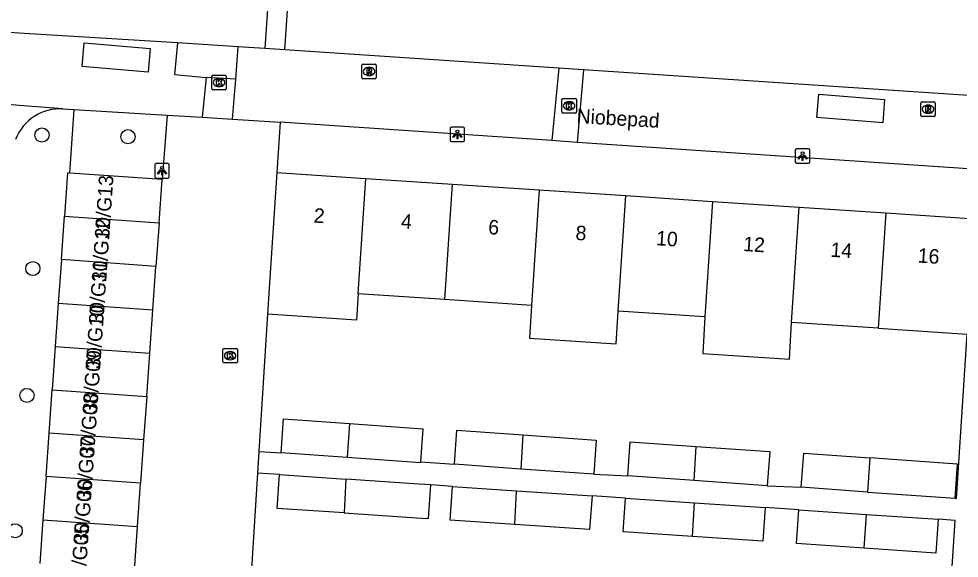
# Model space of a CAD drawing. Extents: x 161848 to 162726, y 385382 to 386521.
# Drawn here: x 162036.5 to 162101.4, y 385774.8 to 385812.1 of the extents above; entities that cross this region are included whole.
import ezdxf

# ---------------------------------------------------------------- set-up
doc = ezdxf.new("R2010")
doc.units = 0
for name, color, linetype in [('IMGEO_Boom', 7, 'Continuous'), ('IMGEO_Kolk', 7, 'Continuous'), ('IMGEO_Lichtpunt', 7, 'Continuous'), ('IMGEO_Muur', 7, 'Continuous'), ('IMGEO_Openbare_ruimte_label', 7, 'Continuous'), ('IMGEO_Pand', 7, 'Continuous'), ('IMGEO_Pand_nummerreeks', 7, 'Continuous'), ('IMGEO_Parkeervlak_open', 7, 'Continuous'), ('IMGEO_Rijbaan_lokaal_open', 7, 'Continuous'), ('IMGEO_Rioolput', 7, 'Continuous'), ('IMGEO_Voetpad_open', 7, 'Continuous'), ('IMGEO_Woonerf_open', 7, 'Continuous')]:
    doc.layers.add(name, color=color, linetype=linetype)

msp = doc.modelspace()

# ---------------------------------------------------------------- linework, layer by layer
at = {"layer": 'IMGEO_Boom'}
for centre in [(162038.108, 385804.041), (162044.038, 385803.929), (162037.475, 385794.824), (162037.071, 385786.061), (162036.258, 385776.72)]:
    msp.add_circle(centre, 0.489, dxfattribs=at)
at = {"layer": 'IMGEO_Kolk'}
for p, q in [((162049.821, 385807.242), (162049.821, 385808.094)), ((162049.896, 385808.168), (162050.748, 385808.168)), ((162050.309, 385807.948), (162050.334, 385807.948)), ((162050.822, 385808.094), (162050.822, 385807.242)), ((162050.332, 385807.388), (162050.307, 385807.388)), ((162050.748, 385807.168), (162049.896, 385807.168)), ((162073.969, 385805.636), (162073.969, 385806.488)), ((162074.044, 385806.562), (162074.896, 385806.562)), ((162074.457, 385806.342), (162074.482, 385806.342)), ((162074.97, 385806.488), (162074.97, 385805.636)), ((162074.896, 385805.562), (162074.044, 385805.562)), ((162074.48, 385805.782), (162074.455, 385805.782)), ((162050.589, 385788.38), (162050.589, 385789.232)), ((162050.664, 385789.306), (162051.516, 385789.306)), ((162051.59, 385789.232), (162051.59, 385788.38)), ((162051.1, 385788.526), (162051.075, 385788.526)), ((162051.077, 385789.086), (162051.102, 385789.086)), ((162051.516, 385788.306), (162050.664, 385788.306))]:
    msp.add_line(p, q, dxfattribs=at)
for points in [[(162049.821, 385807.242), (162049.821, 385808.094)], [(162049.896, 385808.168), (162050.748, 385808.168)], [(162050.822, 385808.094), (162050.822, 385807.242)], [(162050.142, 385807.868), (162050.265, 385807.868), (162050.265, 385807.717), (162050.395, 385807.868), (162050.559, 385807.868), (162050.413, 385807.717), (162050.566, 385807.468), (162050.414, 385807.468), (162050.329, 385807.632), (162050.265, 385807.565), (162050.265, 385807.468), (162050.142, 385807.468), (162050.142, 385807.868)], [(162050.748, 385807.168), (162049.896, 385807.168)], [(162073.969, 385805.636), (162073.969, 385806.488)], [(162074.044, 385806.562), (162074.896, 385806.562)], [(162074.29, 385806.262), (162074.413, 385806.262), (162074.413, 385806.111), (162074.543, 385806.262), (162074.707, 385806.262), (162074.561, 385806.111), (162074.714, 385805.862), (162074.562, 385805.862), (162074.477, 385806.026), (162074.413, 385805.959), (162074.413, 385805.862), (162074.29, 385805.862), (162074.29, 385806.262)], [(162074.97, 385806.488), (162074.97, 385805.636)], [(162074.896, 385805.562), (162074.044, 385805.562)], [(162050.589, 385788.38), (162050.589, 385789.232)], [(162050.664, 385789.306), (162051.516, 385789.306)], [(162051.59, 385789.232), (162051.59, 385788.38)], [(162050.91, 385789.006), (162051.033, 385789.006), (162051.033, 385788.855), (162051.163, 385789.006), (162051.327, 385789.006), (162051.181, 385788.855), (162051.334, 385788.606), (162051.182, 385788.606), (162051.097, 385788.77), (162051.033, 385788.703), (162051.033, 385788.606), (162050.91, 385788.606), (162050.91, 385789.006)], [(162051.516, 385788.306), (162050.664, 385788.306)]]:
    msp.add_lwpolyline(points, dxfattribs=at)
for centre, start, end in [((162049.898, 385808.092), 91.55205, 178.44795), ((162049.898, 385808.092), 91.55205, 178.44795), ((162050.746, 385808.092), 1.55205, 88.44795), ((162050.746, 385808.092), 1.55205, 88.44795), ((162049.898, 385807.244), 181.55205, 268.44795), ((162049.898, 385807.244), 181.55205, 268.44795), ((162050.746, 385807.244), 271.55205, 358.44795), ((162050.746, 385807.244), 271.55205, 358.44795), ((162074.046, 385806.486), 91.55205, 178.44795), ((162074.046, 385806.486), 91.55205, 178.44795), ((162074.894, 385806.486), 1.55205, 88.44795), ((162074.894, 385806.486), 1.55205, 88.44795), ((162074.046, 385805.638), 181.55205, 268.44795), ((162074.046, 385805.638), 181.55205, 268.44795), ((162074.894, 385805.638), 271.55205, 358.44795), ((162074.894, 385805.638), 271.55205, 358.44795), ((162050.666, 385789.23), 91.55205, 178.44795), ((162050.666, 385789.23), 91.55205, 178.44795), ((162051.514, 385789.23), 1.55205, 88.44795), ((162051.514, 385789.23), 1.55205, 88.44795), ((162050.666, 385788.382), 181.55205, 268.44795), ((162050.666, 385788.382), 181.55205, 268.44795), ((162051.514, 385788.382), 271.55205, 358.44795), ((162051.514, 385788.382), 271.55205, 358.44795)]:
    msp.add_arc(centre, 0.0765, start, end, dxfattribs=at)
for centre, major_axis, ratio, start_param, end_param in [((162050.308, 385807.668), (-0.387, 0.002), 0.722429, 4.712389, 7.853982), ((162050.333, 385807.668), (-0.39, 0.002), 0.717154, 1.570796, 4.712389), ((162074.456, 385806.062), (-0.387, 0.002), 0.722429, 4.712389, 7.853982), ((162074.481, 385806.062), (-0.39, 0.002), 0.717154, 1.570796, 4.712389), ((162051.076, 385788.806), (-0.387, 0.002), 0.722429, 4.712389, 7.853982), ((162051.101, 385788.806), (-0.39, 0.002), 0.717154, 1.570796, 4.712389)]:
    msp.add_ellipse(centre, major_axis=major_axis, ratio=ratio, start_param=start_param, end_param=end_param, dxfattribs=at)
at = {"layer": 'IMGEO_Lichtpunt'}
for p, q in [((162066.266, 385804.49), (162066.266, 385803.683)), ((162066.266, 385804.49), (162066.266, 385803.683)), ((162067.168, 385804.585), (162066.36, 385804.585)), ((162067.168, 385804.585), (162066.36, 385804.585)), ((162067.262, 385803.683), (162067.262, 385804.49)), ((162067.262, 385803.683), (162067.262, 385804.49)), ((162066.36, 385803.589), (162067.168, 385803.589)), ((162066.36, 385803.589), (162067.168, 385803.589)), ((162090.073, 385802.993), (162090.073, 385802.186)), ((162090.073, 385802.993), (162090.073, 385802.186)), ((162090.975, 385803.088), (162090.167, 385803.088)), ((162090.975, 385803.088), (162090.167, 385803.088)), ((162091.069, 385802.186), (162091.069, 385802.993)), ((162091.069, 385802.186), (162091.069, 385802.993)), ((162045.894, 385801.975), (162045.894, 385801.168)), ((162045.894, 385801.975), (162045.894, 385801.168)), ((162046.796, 385802.07), (162045.988, 385802.07)), ((162046.796, 385802.07), (162045.988, 385802.07)), ((162046.89, 385801.168), (162046.89, 385801.975)), ((162046.89, 385801.168), (162046.89, 385801.975)), ((162090.167, 385802.092), (162090.975, 385802.092)), ((162090.167, 385802.092), (162090.975, 385802.092)), ((162045.988, 385801.074), (162046.796, 385801.074)), ((162045.988, 385801.074), (162046.796, 385801.074))]:
    msp.add_line(p, q, dxfattribs=at)
for points in [[(162066.64, 385804.154), (162066.679, 385804.126), (162066.491, 385803.864), (162066.453, 385803.891), (162066.64, 385804.154)], [(162066.742, 385804.106), (162066.789, 385804.106), (162066.789, 385803.784), (162066.742, 385803.784), (162066.742, 385804.106)], [(162066.852, 385804.126), (162066.89, 385804.153), (162067.077, 385803.891), (162067.038, 385803.863), (162066.852, 385804.126)], [(162090.447, 385802.657), (162090.486, 385802.629), (162090.298, 385802.367), (162090.26, 385802.394), (162090.447, 385802.657)], [(162090.549, 385802.609), (162090.596, 385802.609), (162090.596, 385802.287), (162090.549, 385802.287), (162090.549, 385802.609)], [(162090.659, 385802.629), (162090.697, 385802.656), (162090.884, 385802.394), (162090.845, 385802.366), (162090.659, 385802.629)], [(162046.268, 385801.639), (162046.307, 385801.611), (162046.119, 385801.349), (162046.081, 385801.376), (162046.268, 385801.639)], [(162046.37, 385801.591), (162046.417, 385801.591), (162046.417, 385801.269), (162046.37, 385801.269), (162046.37, 385801.591)], [(162046.48, 385801.611), (162046.518, 385801.638), (162046.705, 385801.376), (162046.666, 385801.348), (162046.48, 385801.611)]]:
    msp.add_lwpolyline(points, dxfattribs=at)
for centre in [(162066.765, 385804.288), (162090.572, 385802.791), (162046.393, 385801.773)]:
    msp.add_circle(centre, 0.0994, dxfattribs=at)
for centre, start, end in [((162066.36, 385804.49), 90, 180), ((162066.36, 385804.49), 90, 180), ((162067.168, 385804.49), 0, 90), ((162067.168, 385804.49), 0, 90), ((162066.36, 385803.683), 180, 270), ((162066.36, 385803.683), 180, 270), ((162067.168, 385803.683), 270, 0), ((162067.168, 385803.683), 270, 360), ((162090.167, 385802.993), 90, 180), ((162090.167, 385802.993), 90, 180), ((162090.975, 385802.993), 0, 90), ((162090.975, 385802.993), 0, 90), ((162090.167, 385802.186), 180, 270), ((162090.167, 385802.186), 180, 270), ((162090.975, 385802.186), 270, 0), ((162090.975, 385802.186), 270, 360), ((162045.988, 385801.975), 90, 180), ((162045.988, 385801.975), 90, 180), ((162046.796, 385801.975), 0, 90), ((162046.796, 385801.975), 0, 90), ((162045.988, 385801.168), 180, 270), ((162045.988, 385801.168), 180, 270), ((162046.796, 385801.168), 270, 0), ((162046.796, 385801.168), 270, 360)]:
    msp.add_arc(centre, 0.0946, start, end, dxfattribs=at)
at = {"layer": 'IMGEO_Muur'}
for points in [[(162053.668, 385791.676), (162053.076, 385782.207)], [(162052.981, 385780.697), (162052.24, 385768.934)]]:
    msp.add_lwpolyline(points, dxfattribs=at)
at = {"layer": 'IMGEO_Pand'}
for points in [[(162040.02, 385801.419), (162039.87, 385801.43), (162039.658, 385798.434)], [(162046.393, 385800.969), (162040.02, 385801.419)], [(162046.181, 385797.973), (162046.393, 385800.969)], [(162054.315, 385801.455), (162053.787, 385793.481), (162053.668, 385791.676)], [(162054.315, 385801.455), (162060.445, 385801.049)], [(162059.917, 385793.074), (162060.445, 385801.049)], [(162060.445, 385801.049), (162066.425, 385800.653)], [(162065.897, 385792.679), (162066.425, 385800.653)], [(162066.425, 385800.653), (162072.405, 385800.257)], [(162072.405, 385800.257), (162071.877, 385792.283)], [(162072.405, 385800.257), (162078.385, 385799.86)], [(162077.857, 385791.888), (162078.385, 385799.86)], [(162078.385, 385799.86), (162084.365, 385799.464)], [(162084.365, 385799.464), (162083.837, 385791.492)], [(162084.365, 385799.464), (162090.345, 385799.068)], [(162089.817, 385791.097), (162090.345, 385799.068)], [(162090.345, 385799.068), (162096.326, 385798.672)], [(162039.446, 385795.438), (162039.658, 385798.434)], [(162039.658, 385798.434), (162046.181, 385797.973)], [(162096.326, 385798.672), (162095.797, 385790.701)], [(162096.326, 385798.672), (162102.455, 385798.266)], [(162046.181, 385797.973), (162045.969, 385794.977)], [(162039.446, 385795.438), (162039.235, 385792.443)], [(162045.969, 385794.977), (162039.446, 385795.438)], [(162045.758, 385791.981), (162045.969, 385794.977)], [(162059.917, 385793.074), (162059.798, 385791.271), (162053.668, 385791.676)], [(162065.897, 385792.679), (162059.917, 385793.074)], [(162039.235, 385792.443), (162039.023, 385789.447)], [(162039.235, 385792.443), (162045.758, 385791.981)], [(162071.877, 385792.283), (162065.897, 385792.679)], [(162045.546, 385788.986), (162045.758, 385791.981)], [(162071.877, 385792.283), (162071.727, 385790.023), (162077.707, 385789.627), (162077.857, 385791.888)], [(162083.837, 385791.492), (162077.857, 385791.888)], [(162083.837, 385791.492), (162083.689, 385788.968), (162089.663, 385788.573), (162089.817, 385791.097)], [(162095.797, 385790.701), (162089.817, 385791.097)], [(162095.797, 385790.701), (162101.927, 385790.293)], [(162039.023, 385789.447), (162038.811, 385786.451)], [(162039.023, 385789.447), (162045.546, 385788.986)], [(162045.334, 385785.99), (162045.546, 385788.986)], [(162038.599, 385783.455), (162038.811, 385786.451)], [(162038.811, 385786.451), (162045.334, 385785.99)], [(162045.334, 385785.99), (162045.122, 385782.994)], [(162054.6, 385782.098), (162054.768, 385784.452), (162059.325, 385784.127)], [(162059.325, 385784.127), (162059.169, 385781.772)], [(162059.325, 385784.127), (162064.384, 385783.766), (162064.219, 385781.474)], [(162038.388, 385780.459), (162038.599, 385783.455)], [(162045.122, 385782.994), (162038.599, 385783.455)], [(162066.56, 385781.306), (162066.728, 385783.66), (162071.285, 385783.335)], [(162071.285, 385783.335), (162071.129, 385780.98)], [(162071.285, 385783.335), (162076.344, 385782.974), (162076.175, 385780.62)], [(162045.122, 385782.994), (162044.911, 385779.998)], [(162078.52, 385780.513), (162078.688, 385782.867), (162083.244, 385782.542)], [(162059.169, 385781.772), (162054.6, 385782.098)], [(162083.088, 385780.187), (162083.244, 385782.542)], [(162083.244, 385782.542), (162088.304, 385782.181), (162088.135, 385779.827)], [(162090.481, 385779.721), (162090.649, 385782.075), (162095.203, 385781.75)], [(162064.219, 385781.474), (162064.215, 385781.412), (162059.169, 385781.772)], [(162095.203, 385781.75), (162095.047, 385779.395)], [(162101.1, 385778.963), (162101.268, 385781.317), (162100.265, 385781.389), (162095.203, 385781.75)], [(162071.129, 385780.98), (162066.56, 385781.306)], [(162076.175, 385780.62), (162071.129, 385780.98)], [(162038.388, 385780.459), (162038.176, 385777.463)], [(162044.911, 385779.998), (162038.388, 385780.459)], [(162058.941, 385777.956), (162054.325, 385778.267), (162054.482, 385780.596)], [(162054.482, 385780.596), (162059.076, 385780.286)], [(162059.076, 385780.286), (162058.941, 385777.956)], [(162064.931, 385779.892), (162064.111, 385779.947), (162059.076, 385780.286)], [(162083.088, 385780.187), (162078.52, 385780.513)], [(162088.135, 385779.827), (162083.088, 385780.187)], [(162044.699, 385777.002), (162044.911, 385779.998)], [(162058.941, 385777.956), (162063.944, 385777.619), (162064.774, 385777.563), (162064.931, 385779.892)], [(162070.734, 385777.153), (162066.265, 385777.454), (162066.422, 385779.783)], [(162066.422, 385779.783), (162070.848, 385779.485)], [(162070.734, 385777.153), (162070.848, 385779.485)], [(162070.848, 385779.485), (162076.051, 385779.134)], [(162095.047, 385779.395), (162090.481, 385779.721)], [(162076.051, 385779.134), (162075.884, 385776.806), (162070.734, 385777.153)], [(162082.971, 385776.321), (162078.206, 385776.642), (162078.363, 385778.971)], [(162078.363, 385778.971), (162083.126, 385778.65)], [(162095.047, 385779.395), (162100.096, 385779.035), (162101.1, 385778.963)], [(162082.971, 385776.321), (162083.126, 385778.65)], [(162087.992, 385778.322), (162087.825, 385775.994), (162082.971, 385776.321)], [(162083.126, 385778.65), (162087.992, 385778.322)], [(162094.828, 385775.514), (162090.147, 385775.829), (162090.304, 385778.158)], [(162090.304, 385778.158), (162094.972, 385777.843)], [(162038.176, 385777.463), (162037.964, 385774.467)], [(162038.176, 385777.463), (162044.699, 385777.002)], [(162094.828, 385775.514), (162094.972, 385777.843)], [(162099.933, 385777.509), (162099.766, 385775.181), (162094.828, 385775.514)], [(162094.972, 385777.843), (162099.933, 385777.509)], [(162044.487, 385774.006), (162044.699, 385777.002)]]:
    msp.add_lwpolyline(points, dxfattribs=at)
at = {"layer": 'IMGEO_Parkeervlak_open'}
for points in [[(162040.879, 385808.765), (162041.017, 385810.398), (162045.563, 385810.014), (162045.425, 385808.381), (162040.879, 385808.765)], [(162047.467, 385810.415), (162047.247, 385808.224), (162049.422, 385808.006)], [(162051.643, 385810.135), (162047.467, 385810.415)], [(162051.472, 385807.904), (162051.643, 385810.135)], [(162051.472, 385807.904), (162049.422, 385808.006)], [(162091.559, 385805.256), (162091.69, 385806.865), (162096.233, 385806.495), (162096.102, 385804.886), (162091.559, 385805.256)]]:
    msp.add_lwpolyline(points, dxfattribs=at)
at = {"layer": 'IMGEO_Rijbaan_lokaal_open'}
for points in [[(162046.739, 385805.425), (162046.393, 385800.969)], [(162046.739, 385805.425), (162049.152, 385805.269)], [(162049.152, 385805.269), (162051.259, 385805.133)], [(162051.259, 385805.133), (162054.532, 385804.921)], [(162054.532, 385804.921), (162054.315, 385801.455)], [(162053.668, 385791.676), (162053.076, 385782.207), (162053.075, 385782.193)], [(162053.075, 385782.193), (162052.981, 385780.697), (162052.981, 385780.69)], [(162052.981, 385780.69), (162052.24, 385768.934)]]:
    msp.add_lwpolyline(points, dxfattribs=at)
at = {"layer": 'IMGEO_Rioolput'}
for p, q in [((162060.169, 385808.006), (162060.169, 385808.858)), ((162060.244, 385808.932), (162061.096, 385808.932)), ((162060.657, 385808.712), (162060.682, 385808.712)), ((162061.17, 385808.858), (162061.17, 385808.006)), ((162060.68, 385808.152), (162060.655, 385808.152)), ((162061.096, 385807.932), (162060.244, 385807.932)), ((162098.726, 385805.398), (162098.726, 385806.25)), ((162098.801, 385806.324), (162099.653, 385806.324)), ((162099.214, 385806.104), (162099.239, 385806.104)), ((162099.727, 385806.25), (162099.727, 385805.398)), ((162099.237, 385805.544), (162099.212, 385805.544)), ((162099.653, 385805.324), (162098.801, 385805.324))]:
    msp.add_line(p, q, dxfattribs=at)
for points in [[(162060.169, 385808.006), (162060.169, 385808.858)], [(162060.244, 385808.932), (162061.096, 385808.932)], [(162060.758, 385808.63), (162060.506, 385808.632), (162060.506, 385808.232)], [(162061.17, 385808.858), (162061.17, 385808.006)], [(162060.506, 385808.232), (162060.63, 385808.232), (162060.63, 385808.394), (162060.641, 385808.394)], [(162060.684, 385808.551), (162060.63, 385808.551), (162060.63, 385808.47)], [(162060.63, 385808.47), (162060.682, 385808.47)], [(162060.688, 385808.365), (162060.759, 385808.232), (162060.899, 385808.232), (162060.834, 385808.358)], [(162061.096, 385807.932), (162060.244, 385807.932)], [(162098.726, 385805.398), (162098.726, 385806.25)], [(162098.801, 385806.324), (162099.653, 385806.324)], [(162099.315, 385806.022), (162099.063, 385806.024), (162099.063, 385805.624)], [(162099.727, 385806.25), (162099.727, 385805.398)], [(162099.063, 385805.624), (162099.187, 385805.624), (162099.187, 385805.786), (162099.198, 385805.786)], [(162099.241, 385805.943), (162099.187, 385805.943), (162099.187, 385805.862)], [(162099.187, 385805.862), (162099.239, 385805.862)], [(162099.245, 385805.757), (162099.316, 385805.624), (162099.456, 385805.624), (162099.391, 385805.75)], [(162099.653, 385805.324), (162098.801, 385805.324)]]:
    msp.add_lwpolyline(points, dxfattribs=at)
for centre, radius, start, end in [((162060.246, 385808.856), 0.0765, 91.55205, 178.44795), ((162060.246, 385808.856), 0.0765, 91.55205, 178.44795), ((162060.757, 385808.52), 0.109, 350.36119, 89.41601), ((162061.094, 385808.856), 0.0765, 1.55205, 88.44795), ((162061.094, 385808.856), 0.0765, 1.55205, 88.44795), ((162060.246, 385808.008), 0.0765, 181.55205, 268.44795), ((162060.246, 385808.008), 0.0765, 181.55205, 268.44795), ((162060.64, 385808.341), 0.0533, 26.02933, 88.69889), ((162060.666, 385808.659), 0.19, 274.7715, 282.96867), ((162060.69, 385808.455), 0.0964, 77.00612, 93.18647), ((162060.704, 385808.512), 0.0378, 276.66336, 79.67722), ((162060.755, 385808.52), 0.112, 277.58423, 350.98172), ((162060.739, 385808.305), 0.108, 29.51342, 73.79051), ((162061.094, 385808.008), 0.0765, 271.55205, 358.44795), ((162061.094, 385808.008), 0.0765, 271.55205, 358.44795), ((162098.803, 385806.248), 0.0765, 91.55205, 178.44795), ((162098.803, 385806.248), 0.0765, 91.55205, 178.44795), ((162099.314, 385805.912), 0.109, 350.36119, 89.41601), ((162099.651, 385806.248), 0.0765, 1.55205, 88.44795), ((162099.651, 385806.248), 0.0765, 1.55205, 88.44795), ((162098.803, 385805.4), 0.0765, 181.55205, 268.44795), ((162098.803, 385805.4), 0.0765, 181.55205, 268.44795), ((162099.197, 385805.733), 0.0533, 26.02933, 88.69889), ((162099.223, 385806.051), 0.19, 274.7715, 282.96867), ((162099.247, 385805.847), 0.0964, 77.00612, 93.18647), ((162099.261, 385805.904), 0.0378, 276.66336, 79.67722), ((162099.312, 385805.912), 0.112, 277.58423, 350.98172), ((162099.296, 385805.697), 0.108, 29.51342, 73.79051), ((162099.651, 385805.4), 0.0765, 271.55205, 358.44795), ((162099.651, 385805.4), 0.0765, 271.55205, 358.44795)]:
    msp.add_arc(centre, radius, start, end, dxfattribs=at)
for centre, major_axis, ratio, start_param, end_param in [((162060.656, 385808.432), (-0.387, 0.002), 0.722429, 4.712389, 7.853982), ((162060.681, 385808.432), (-0.39, 0.002), 0.717154, 1.570796, 4.712389), ((162099.213, 385805.824), (-0.387, 0.002), 0.722429, 4.712389, 7.853982), ((162099.238, 385805.824), (-0.39, 0.002), 0.717154, 1.570796, 4.712389)]:
    msp.add_ellipse(centre, major_axis=major_axis, ratio=ratio, start_param=start_param, end_param=end_param, dxfattribs=at)
at = {"layer": 'IMGEO_Voetpad_open'}
for points in [[(162054.866, 385809.919), (162055.638, 385821.441)], [(162054.183, 385820.545), (162053.477, 385810.012)], [(162054.866, 385809.919), (162053.477, 385810.012)], [(162039.555, 385805.85), (162036.533, 385806.086), (162035.536, 385806.172)], [(162040.02, 385801.419), (162040.331, 385805.804)], [(162040.331, 385805.804), (162046.739, 385805.425)], [(162101.1, 385778.963), (162101.195, 385778.956), (162101.715, 385787.102), (162101.927, 385790.293)], [(162053.075, 385782.193), (162054.6, 385782.098)], [(162064.219, 385781.474), (162066.56, 385781.306)], [(162054.482, 385780.596), (162052.981, 385780.69)], [(162076.175, 385780.62), (162078.52, 385780.513)], [(162066.422, 385779.783), (162064.931, 385779.892)], [(162088.135, 385779.827), (162090.481, 385779.721)], [(162078.363, 385778.971), (162076.051, 385779.134)], [(162090.304, 385778.158), (162087.992, 385778.322)], [(162100.343, 385765.734), (162101.098, 385777.434), (162099.933, 385777.509)]]:
    msp.add_lwpolyline(points, dxfattribs=at)
msp.add_arc((162039.366, 385802.564), 3.291, 86.70943, 159.06755, dxfattribs=at)
at = {"layer": 'IMGEO_Woonerf_open'}
for points in [[(162047.467, 385810.415), (162036.872, 385811.045), (162035.875, 385811.129)], [(162053.477, 385810.012), (162051.643, 385810.135)], [(162073.751, 385808.654), (162054.866, 385809.919)], [(162073.751, 385808.654), (162073.287, 385803.655)], [(162075.471, 385808.539), (162073.751, 385808.654)], [(162049.422, 385808.006), (162049.152, 385805.269)], [(162075.471, 385808.539), (162075.031, 385803.537)], [(162103.056, 385806.692), (162075.471, 385808.539)], [(162051.259, 385805.133), (162051.472, 385807.904)], [(162039.555, 385805.85), (162040.331, 385805.804)], [(162073.287, 385803.655), (162054.532, 385804.921)], [(162075.031, 385803.537), (162073.287, 385803.655)], [(162102.685, 385801.671), (162075.031, 385803.537)]]:
    msp.add_lwpolyline(points, dxfattribs=at)

# ---------------------------------------------------------------- texts
at = {"layer": 'IMGEO_Openbare_ruimte_label'}
msp.add_text('Niobepad', height=1, rotation=356.67393, dxfattribs=at).set_placement((162074.965, 385804.869))
at = {"layer": 'IMGEO_Pand_nummerreeks'}
for s, rotation, p in [('30/G13', 86.02327, (162042.74, 385796.859)), ('2', 356.21002, (162056.83, 385798.001)), ('4', 356.21002, (162062.85, 385797.602)), ('30/G12', 86.02327, (162042.532, 385793.856)), ('6', 356.21002, (162068.867, 385797.204)), ('8', 356.21275, (162074.889, 385796.805)), ('10', 356.21002, (162080.446, 385796.438)), ('12', 356.21275, (162086.457, 385796.038)), ('14', 356.21002, (162092.478, 385795.64)), ('16', 356.21275, (162098.495, 385795.241)), ('30/G11', 86.02327, (162042.331, 385790.976)), ('30/G10', 86.02327, (162042.116, 385787.872)), ('30/G09', 86.02327, (162041.901, 385784.778)), ('30/G08', 86.02327, (162041.693, 385781.787)), ('30/G07', 86.02327, (162041.484, 385778.788)), ('30/G06', 86.02327, (162041.276, 385775.791)), ('30/G05', 86.02327, (162041.067, 385772.794))]:
    msp.add_text(s, height=1, rotation=rotation, dxfattribs=at).set_placement(p)

doc.saveas('drawing.dxf')
